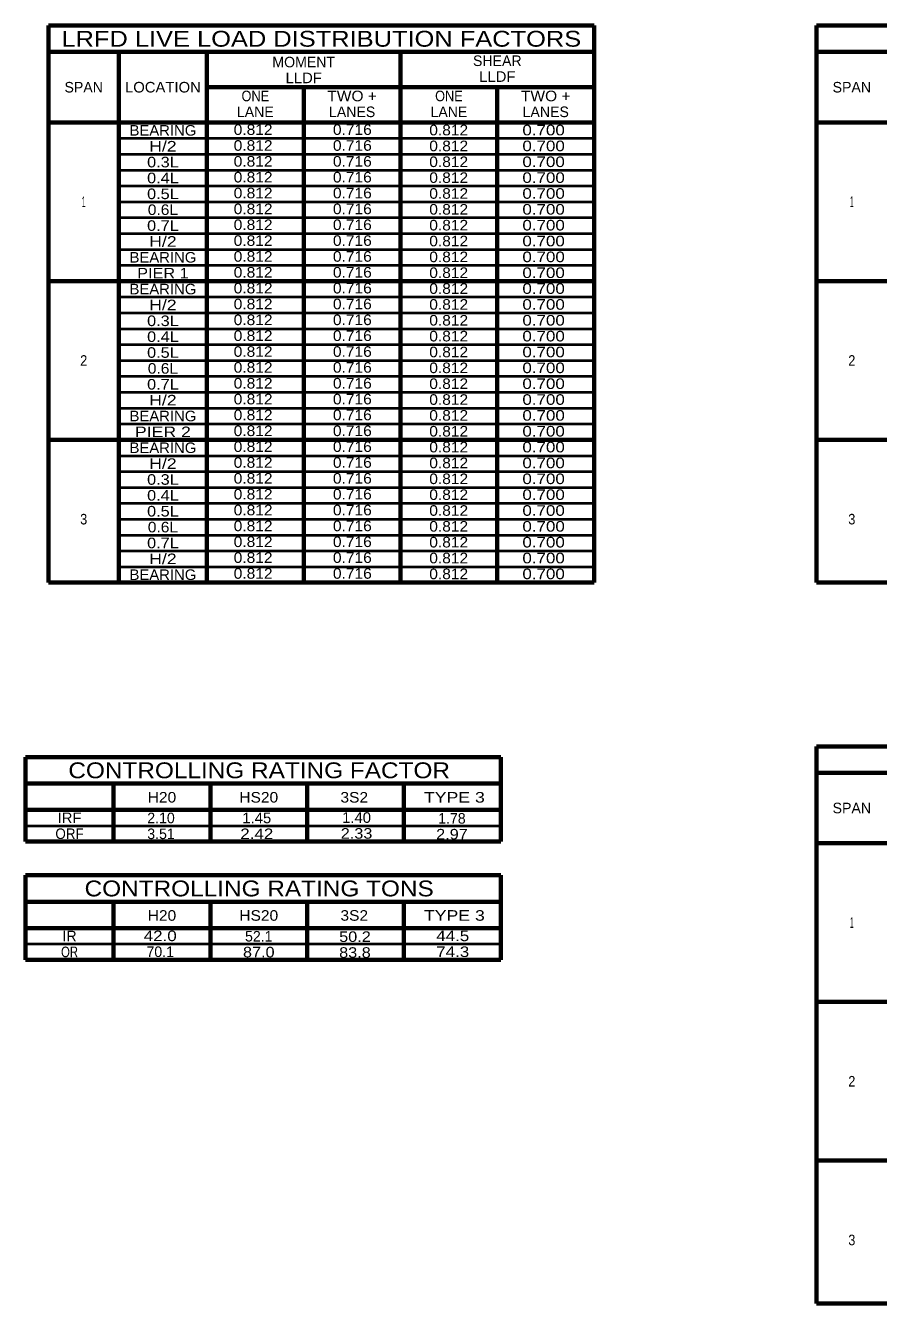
# Model space of a CAD drawing. Extents: x -2055 to -1915, y -81 to 6.
# Drawn here: x -2054.7 to -2006.2, y -66.8 to 5.8 of the extents above; entities that cross this region are included whole.
import ezdxf
from ezdxf.enums import TextEntityAlignment as Align

# ---------------------------------------------------------------- set-up
doc = ezdxf.new("R2010")
doc.units = 0
doc.header["$LTSCALE"] = 0.24
doc.layers.add('1', color=7, linetype='Continuous', lineweight=70)
doc.layers.add('5', color=7, linetype='Continuous', lineweight=40)
doc.layers.add('21', color=7, linetype='Continuous')
doc.layers.add('9', color=7, linetype='Continuous')

msp = doc.modelspace()

# ---------------------------------------------------------------- linework, layer by layer
at = {"layer": '1'}
for p, q in [((-2053.3937, 5.7798), (-2053.3937, -25.8503)), ((-2053.3937, 5.7798), (-2022.3937, 5.7798)), ((-2022.3937, 5.7798), (-2022.3937, -25.8503)), ((-2009.7523, 5.7798), (-2009.7523, -25.8503)), ((-2009.7523, 5.7798), (-1923.7523, 5.7798)), ((-2053.3937, 4.2798), (-2022.3937, 4.2798)), ((-2049.3937, 4.2798), (-2049.3937, -25.8503)), ((-2044.3937, 4.2798), (-2044.3937, -25.8503)), ((-2033.3937, 4.2798), (-2033.3937, -25.8503)), ((-2009.7523, 4.2798), (-1923.7523, 4.2798)), ((-2044.3937, 2.2798), (-2022.3937, 2.2798)), ((-2038.8937, 2.2798), (-2038.8937, -25.8503)), ((-2027.8937, 2.2798), (-2027.8937, -25.8503)), ((-2053.3937, 0.2798), (-2022.3937, 0.2798)), ((-2009.7523, 0.2798), (-1923.7523, 0.2798)), ((-2053.3937, -8.7306), (-2022.3937, -8.7306)), ((-2009.7523, -8.7306), (-1923.7523, -8.7306)), ((-2053.3937, -17.741), (-2022.3937, -17.741)), ((-2009.7523, -17.741), (-1923.7523, -17.741)), ((-2053.3937, -25.8503), (-2022.3937, -25.8503)), ((-2009.7523, -25.8503), (-1923.7523, -25.8503)), ((-2009.7523, -35.1469), (-1923.7523, -35.1469)), ((-2009.7523, -35.1469), (-2009.7523, -66.7771)), ((-2054.6985, -35.7556), (-2027.6985, -35.7556)), ((-2054.6985, -35.7556), (-2054.6985, -40.5577)), ((-2027.6985, -35.7556), (-2027.6985, -40.5577)), ((-2009.7523, -36.6469), (-1923.7523, -36.6469)), ((-2054.6985, -37.2556), (-2027.6985, -37.2556)), ((-2049.6985, -37.2556), (-2049.6985, -40.5577)), ((-2044.1985, -37.2556), (-2044.1985, -40.5577)), ((-2038.6985, -37.2556), (-2038.6985, -40.5577)), ((-2033.1985, -37.2556), (-2033.1985, -40.5577)), ((-2054.6985, -38.7556), (-2027.6985, -38.7556)), ((-2054.6985, -40.5577), (-2027.6985, -40.5577)), ((-2009.7523, -40.6469), (-1923.7523, -40.6469)), ((-2054.6985, -42.4648), (-2027.6985, -42.4648)), ((-2054.6985, -42.4648), (-2054.6985, -47.2669)), ((-2027.6985, -42.4648), (-2027.6985, -47.2669)), ((-2054.6985, -43.9648), (-2027.6985, -43.9648)), ((-2049.6985, -43.9648), (-2049.6985, -47.2669)), ((-2044.1985, -43.9648), (-2044.1985, -47.2669)), ((-2038.6985, -43.9648), (-2038.6985, -47.2669)), ((-2033.1985, -43.9648), (-2033.1985, -47.2669)), ((-2054.6985, -45.4648), (-2027.6985, -45.4648)), ((-2054.6985, -47.2669), (-2027.6985, -47.2669)), ((-2009.7523, -49.6573), (-1923.7523, -49.6573)), ((-2009.7523, -58.6677), (-1923.7523, -58.6677)), ((-2009.7523, -66.7771), (-1923.7523, -66.7771))]:
    msp.add_line(p, q, dxfattribs=at)
at = {"layer": '5'}
for p, q in [((-2049.3937, -0.6212), (-2022.3937, -0.6212)), ((-2049.3937, -1.5222), (-2022.3937, -1.5222)), ((-2049.3937, -2.4232), (-2022.3937, -2.4232)), ((-2049.3937, -3.3243), (-2022.3937, -3.3243)), ((-2049.3937, -4.2253), (-2022.3937, -4.2253)), ((-2049.3937, -5.1264), (-2022.3937, -5.1264)), ((-2049.3937, -6.0274), (-2022.3937, -6.0274)), ((-2049.3937, -6.9285), (-2022.3937, -6.9285)), ((-2049.3937, -7.8295), (-2022.3937, -7.8295)), ((-2049.3937, -9.6316), (-2022.3937, -9.6316)), ((-2049.3937, -10.5327), (-2022.3937, -10.5327)), ((-2049.3937, -11.4337), (-2022.3937, -11.4337)), ((-2049.3937, -12.3347), (-2022.3937, -12.3347)), ((-2049.3937, -13.2357), (-2022.3937, -13.2357)), ((-2049.3937, -14.1368), (-2022.3937, -14.1368)), ((-2049.3937, -15.0378), (-2022.3937, -15.0378)), ((-2049.3937, -15.9389), (-2022.3937, -15.9389)), ((-2049.3937, -16.8399), (-2022.3937, -16.8399)), ((-2049.3937, -18.642), (-2022.3937, -18.642)), ((-2049.3937, -19.5431), (-2022.3937, -19.5431)), ((-2049.3937, -20.4441), (-2022.3937, -20.4441)), ((-2049.3937, -21.3452), (-2022.3937, -21.3452)), ((-2049.3937, -22.2462), (-2022.3937, -22.2462)), ((-2049.3937, -23.1472), (-2022.3937, -23.1472)), ((-2049.3937, -24.0482), (-2022.3937, -24.0482)), ((-2049.3937, -24.9493), (-2022.3937, -24.9493)), ((-2054.6985, -39.6566), (-2027.6985, -39.6566)), ((-2054.6985, -46.3659), (-2027.6985, -46.3659))]:
    msp.add_line(p, q, dxfattribs=at)

# ---------------------------------------------------------------- texts
at = {"layer": '1'}
for s, width, p in [('BEARING', 1.05, (-2046.8933, -0.4707)), ('H/2', 1.25, (-2046.8935, -1.3717)), ('0.3L', 1.15, (-2046.8935, -2.2727)), ('0.4L', 1.15, (-2046.8935, -3.1738)), ('0.5L', 1.15, (-2046.8935, -4.0748)), ('0.6L', 1.1, (-2046.8934, -4.9758)), ('0.7L', 1.15, (-2046.8935, -5.8769)), ('H/2', 1.25, (-2046.8935, -6.7779)), ('BEARING', 1.05, (-2046.8933, -7.679)), ('PIER 1', 1.15, (-2046.8934, -8.58)), ('BEARING', 1.05, (-2046.8933, -9.4811)), ('H/2', 1.25, (-2046.8935, -10.3821)), ('0.3L', 1.15, (-2046.8935, -11.2832)), ('0.4L', 1.15, (-2046.8935, -12.1842)), ('0.5L', 1.15, (-2046.8935, -13.0853)), ('0.6L', 1.1, (-2046.8934, -13.9863)), ('0.7L', 1.15, (-2046.8935, -14.8873)), ('H/2', 1.25, (-2046.8935, -15.7883)), ('BEARING', 1.05, (-2046.8933, -16.6894)), ('PIER 2', 1.25, (-2046.8934, -17.5904)), ('BEARING', 1.05, (-2046.8933, -18.4915)), ('H/2', 1.25, (-2046.8935, -19.3925)), ('0.3L', 1.15, (-2046.8935, -20.2936)), ('0.4L', 1.15, (-2046.8935, -21.1946)), ('0.5L', 1.15, (-2046.8935, -22.0957)), ('0.6L', 1.1, (-2046.8934, -22.9967)), ('0.7L', 1.15, (-2046.8935, -23.8977)), ('H/2', 1.25, (-2046.8935, -24.7987)), ('BEARING', 1.05, (-2046.8933, -25.6998)), ('IRF', 1.05, (-2052.1983, -39.5061)), ('ORF', 0.95, (-2052.1984, -40.4072)), ('OR', 0.8, (-2052.1983, -47.1164))]:
    msp.add_text(s, height=0.6, dxfattribs=dict(at, width=width)).set_placement(p, align=Align.CENTER)
msp.add_text('IR', height=0.6, dxfattribs=at).set_placement((-2052.1983, -46.2153), align=Align.CENTER)
at = {"layer": '21'}
for s, p in [('MOMENT', (-2038.8935, 3.408)), ('SHEAR', (-2027.8934, 3.4822)), ('SPAN', (-2051.3935, 1.9798)), ('SPAN', (-2007.7521, 1.9798)), ('LANE', (-2041.6434, 0.5822)), ('LANES', (-2036.1435, 0.5822)), ('LANE', (-2030.6434, 0.5822)), ('LANES', (-2025.1435, 0.5822)), ('SPAN', (-2007.7521, -38.9469)), ('2.10', (-2047.0017, -39.5112)), ('1.78', (-2030.4721, -39.5338)), ('3.51', (-2047.0018, -40.4112)), ('52.1', (-2041.4468, -46.2293)), ('70.1', (-2047.0469, -47.1067))]:
    msp.add_text(s, height=0.6, dxfattribs=at).set_placement(p, align=Align.CENTER)
for s, width, p in [('LLDF', 1.05, (-2038.8934, 2.508)), ('LLDF', 1.05, (-2027.8934, 2.5822)), ('LOCATION', 1.05, (-2046.8934, 1.9798)), ('ONE', 0.9, (-2041.6434, 1.4822)), ('TWO +', 1.1, (-2036.1435, 1.4822)), ('ONE', 0.9, (-2030.6434, 1.4822)), ('TWO +', 1.1, (-2025.1435, 1.4822)), ('1', 0.4, (-2051.3935, -4.5253)), ('1', 0.4, (-2007.7521, -4.5253)), ('2', 0.9, (-2051.3933, -13.5358)), ('2', 0.9, (-2007.752, -13.5358)), ('3', 0.9, (-2051.3933, -22.5462)), ('3', 0.9, (-2007.752, -22.5462)), ('H20', 1.1, (-2046.9484, -38.338)), ('HS20', 1.1, (-2041.4484, -38.338)), ('3S2', 1.1, (-2036.0218, -38.338)), ('TYPE 3', 1.25, (-2030.3325, -38.338)), ('1.45', 1.05, (-2041.5597, -39.5112)), ('1.40', 1.05, (-2035.8917, -39.4887)), ('2.42', 1.2, (-2041.5597, -40.4112)), ('2.33', 1.15, (-2035.8917, -40.3888)), ('2.97', 1.15, (-2030.4721, -40.4338)), ('H20', 1.1, (-2046.9484, -45.0472)), ('HS20', 1.1, (-2041.4484, -45.0472)), ('3S2', 1.1, (-2036.0218, -45.0472)), ('TYPE 3', 1.25, (-2030.3325, -45.0472)), ('1', 0.4, (-2007.7521, -45.4521)), ('42.0', 1.2, (-2047.047, -46.2067)), ('50.2', 1.15, (-2035.982, -46.2518)), ('44.5', 1.2, (-2030.427, -46.2067)), ('87.0', 1.15, (-2041.4468, -47.1292)), ('83.8', 1.15, (-2035.982, -47.1518)), ('74.3', 1.2, (-2030.427, -47.1067)), ('2', 0.9, (-2007.752, -54.4625)), ('3', 0.9, (-2007.752, -63.4729))]:
    msp.add_text(s, height=0.6, dxfattribs=dict(at, width=width)).set_placement(p, align=Align.CENTER)
at = {"layer": '9'}
for s, height, width, p in [('LRFD LIVE LOAD DISTRIBUTION FACTORS', 0.9, 1.2, (-2037.8931, 4.5798)), ('0.812', 0.6, 1.1, (-2041.7683, -0.4293)), ('0.716', 0.6, 1.1, (-2036.1299, -0.4293)), ('0.812', 0.6, 1.1, (-2030.6558, -0.454)), ('0.700', 0.6, 1.2, (-2025.264, -0.454)), ('0.812', 0.6, 1.1, (-2041.7683, -1.3293)), ('0.716', 0.6, 1.1, (-2036.1299, -1.3293)), ('0.812', 0.6, 1.1, (-2030.6558, -1.354)), ('0.700', 0.6, 1.2, (-2025.264, -1.354)), ('0.812', 0.6, 1.1, (-2041.7683, -2.2293)), ('0.716', 0.6, 1.1, (-2036.1299, -2.2293)), ('0.812', 0.6, 1.1, (-2030.6558, -2.254)), ('0.700', 0.6, 1.2, (-2025.264, -2.254)), ('0.812', 0.6, 1.1, (-2041.7683, -3.1293)), ('0.716', 0.6, 1.1, (-2036.1299, -3.1293)), ('0.812', 0.6, 1.1, (-2030.6558, -3.154)), ('0.700', 0.6, 1.2, (-2025.264, -3.154)), ('0.812', 0.6, 1.1, (-2041.7683, -4.0293)), ('0.716', 0.6, 1.1, (-2036.1299, -4.0293)), ('0.812', 0.6, 1.1, (-2030.6558, -4.054)), ('0.700', 0.6, 1.2, (-2025.264, -4.054)), ('0.812', 0.6, 1.1, (-2041.7683, -4.9293)), ('0.716', 0.6, 1.1, (-2036.1299, -4.9293)), ('0.812', 0.6, 1.1, (-2030.6558, -4.954)), ('0.700', 0.6, 1.2, (-2025.264, -4.954)), ('0.812', 0.6, 1.1, (-2041.7683, -5.8293)), ('0.716', 0.6, 1.1, (-2036.1299, -5.8293)), ('0.812', 0.6, 1.1, (-2030.6558, -5.854)), ('0.700', 0.6, 1.2, (-2025.264, -5.854)), ('0.812', 0.6, 1.1, (-2041.7683, -6.7293)), ('0.716', 0.6, 1.1, (-2036.1299, -6.7293)), ('0.812', 0.6, 1.1, (-2030.6558, -6.754)), ('0.700', 0.6, 1.2, (-2025.264, -6.754)), ('0.812', 0.6, 1.1, (-2041.7683, -7.6293)), ('0.716', 0.6, 1.1, (-2036.1299, -7.6293)), ('0.812', 0.6, 1.1, (-2030.6558, -7.654)), ('0.700', 0.6, 1.2, (-2025.264, -7.654)), ('0.812', 0.6, 1.1, (-2041.7683, -8.5293)), ('0.716', 0.6, 1.1, (-2036.1299, -8.5293)), ('0.812', 0.6, 1.1, (-2030.6558, -8.554)), ('0.700', 0.6, 1.2, (-2025.264, -8.554)), ('0.812', 0.6, 1.1, (-2041.7683, -9.4293)), ('0.716', 0.6, 1.1, (-2036.1299, -9.4293)), ('0.812', 0.6, 1.1, (-2030.6558, -9.454)), ('0.700', 0.6, 1.2, (-2025.264, -9.454)), ('0.812', 0.6, 1.1, (-2041.7683, -10.3293)), ('0.716', 0.6, 1.1, (-2036.1299, -10.3293)), ('0.812', 0.6, 1.1, (-2030.6558, -10.354)), ('0.700', 0.6, 1.2, (-2025.264, -10.354)), ('0.812', 0.6, 1.1, (-2041.7683, -11.2293)), ('0.716', 0.6, 1.1, (-2036.1299, -11.2293)), ('0.812', 0.6, 1.1, (-2030.6558, -11.254)), ('0.700', 0.6, 1.2, (-2025.264, -11.254)), ('0.812', 0.6, 1.1, (-2041.7683, -12.1293)), ('0.716', 0.6, 1.1, (-2036.1299, -12.1293)), ('0.812', 0.6, 1.1, (-2030.6558, -12.154)), ('0.700', 0.6, 1.2, (-2025.264, -12.154)), ('0.812', 0.6, 1.1, (-2041.7683, -13.0293)), ('0.716', 0.6, 1.1, (-2036.1299, -13.0293)), ('0.812', 0.6, 1.1, (-2030.6558, -13.054)), ('0.700', 0.6, 1.2, (-2025.264, -13.054)), ('0.812', 0.6, 1.1, (-2041.7683, -13.9293)), ('0.716', 0.6, 1.1, (-2036.1299, -13.9293)), ('0.812', 0.6, 1.1, (-2030.6558, -13.954)), ('0.700', 0.6, 1.2, (-2025.264, -13.954)), ('0.812', 0.6, 1.1, (-2041.7683, -14.8293)), ('0.716', 0.6, 1.1, (-2036.1299, -14.8293)), ('0.812', 0.6, 1.1, (-2030.6558, -14.854)), ('0.700', 0.6, 1.2, (-2025.264, -14.854)), ('0.812', 0.6, 1.1, (-2041.7683, -15.7293)), ('0.716', 0.6, 1.1, (-2036.1299, -15.7293)), ('0.812', 0.6, 1.1, (-2030.6558, -15.754)), ('0.700', 0.6, 1.2, (-2025.264, -15.754)), ('0.812', 0.6, 1.1, (-2041.7683, -16.6293)), ('0.716', 0.6, 1.1, (-2036.1299, -16.6293)), ('0.812', 0.6, 1.1, (-2030.6558, -16.654)), ('0.700', 0.6, 1.2, (-2025.264, -16.654)), ('0.812', 0.6, 1.1, (-2041.7683, -17.5293)), ('0.716', 0.6, 1.1, (-2036.1299, -17.5293)), ('0.812', 0.6, 1.1, (-2030.6558, -17.554)), ('0.700', 0.6, 1.2, (-2025.264, -17.554)), ('0.812', 0.6, 1.1, (-2041.7683, -18.4293)), ('0.716', 0.6, 1.1, (-2036.1299, -18.4293)), ('0.812', 0.6, 1.1, (-2030.6558, -18.454)), ('0.700', 0.6, 1.2, (-2025.264, -18.454)), ('0.812', 0.6, 1.1, (-2041.7683, -19.3293)), ('0.716', 0.6, 1.1, (-2036.1299, -19.3293)), ('0.812', 0.6, 1.1, (-2030.6558, -19.354)), ('0.700', 0.6, 1.2, (-2025.264, -19.354)), ('0.812', 0.6, 1.1, (-2041.7683, -20.2293)), ('0.716', 0.6, 1.1, (-2036.1299, -20.2293)), ('0.812', 0.6, 1.1, (-2030.6558, -20.254)), ('0.700', 0.6, 1.2, (-2025.264, -20.254)), ('0.812', 0.6, 1.1, (-2041.7683, -21.1293)), ('0.716', 0.6, 1.1, (-2036.1299, -21.1293)), ('0.812', 0.6, 1.1, (-2030.6558, -21.154)), ('0.700', 0.6, 1.2, (-2025.264, -21.154)), ('0.812', 0.6, 1.1, (-2041.7683, -22.0293)), ('0.716', 0.6, 1.1, (-2036.1299, -22.0293)), ('0.812', 0.6, 1.1, (-2030.6558, -22.054)), ('0.700', 0.6, 1.2, (-2025.264, -22.054)), ('0.812', 0.6, 1.1, (-2041.7683, -22.9293)), ('0.716', 0.6, 1.1, (-2036.1299, -22.9293)), ('0.812', 0.6, 1.1, (-2030.6558, -22.954)), ('0.700', 0.6, 1.2, (-2025.264, -22.954)), ('0.812', 0.6, 1.1, (-2041.7683, -23.8293)), ('0.716', 0.6, 1.1, (-2036.1299, -23.8293)), ('0.812', 0.6, 1.1, (-2030.6558, -23.854)), ('0.700', 0.6, 1.2, (-2025.264, -23.854)), ('0.812', 0.6, 1.1, (-2041.7683, -24.7293)), ('0.716', 0.6, 1.1, (-2036.1299, -24.7293)), ('0.812', 0.6, 1.1, (-2030.6558, -24.754)), ('0.700', 0.6, 1.2, (-2025.264, -24.754)), ('0.812', 0.6, 1.1, (-2041.7683, -25.6293)), ('0.716', 0.6, 1.1, (-2036.1299, -25.6293)), ('0.812', 0.6, 1.1, (-2030.6558, -25.654)), ('0.700', 0.6, 1.2, (-2025.264, -25.654)), ('CONTROLLING RATING FACTOR', 0.9, 1.15, (-2041.425, -36.9556)), ('CONTROLLING RATING TONS', 0.9, 1.15, (-2041.4247, -43.6648))]:
    msp.add_text(s, height=height, dxfattribs=dict(at, width=width)).set_placement(p, align=Align.CENTER)

doc.saveas('drawing.dxf')
